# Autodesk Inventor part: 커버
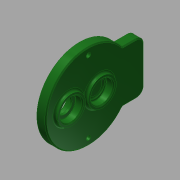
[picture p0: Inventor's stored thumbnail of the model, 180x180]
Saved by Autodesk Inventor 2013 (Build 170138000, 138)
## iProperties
Created: 2016-02
Part Number: 커버
Material: 일반
Document SubType Name: Modeling
Designer: mduedu
Density: 1 g/cm^3
Mass: 58.0249 g
Surface Area: 178.476 cm^2
Volume: 58.0249 cm^3
Author: mduedu
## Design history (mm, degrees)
sketch "스케치1"
  geometry: C1 r 43 at (0, 0); 1 further point
  constraints: 1 centre point, 1 coincident
  dimensions: "d0" = 86 diameter of C1
extrude "돌출1" new body sketch "스케치1" distance "d1" = 9; taper "d2" = 0 deg
sketch "스케치2"
  geometry: C1 r 14 at (0, 11); 1 further point
  constraints: 1 centre point, 1 vertical alignment
  dimensions: "d3" = 28 diameter of C1; "d6" = 11 distance of C1.centre point (0, 0)
extrude "돌출2" join sketch "스케치2" distance "d7" = 3; taper "d8" = 0 deg
sketch "스케치3"
  geometry: C1 r 14 at (0, -20); 1 further point
  constraints: 1 centre point, 1 vertical alignment
  dimensions: "d9" = 28 diameter of C1; "d10" = 20 distance of C1.centre point (0, 0)
extrude "돌출3" join sketch "스케치3" distance "d11" = 3; taper "d12" = 0 deg
hole "구멍1" diameter "d15" = 22; stored, may be unused: countersink angle "d19" = 90 deg, drill point angle "d21" = 0 deg; dims "d13" = 10, "d14" = 10, "d16" = 6, "d17" = 4, "d18" = 2, "d20" = 7
hole "구멍2" diameter "d24" = 18; stored, may be unused: countersink angle "d28" = 90 deg, drill point angle "d30" = 0 deg; dims "d22" = 10, "d23" = 10, "d25" = 6, "d26" = 4, "d27" = 2, "d29" = 1
hole "구멍3" diameter "d33" = 22; stored, may be unused: countersink angle "d37" = 90 deg, drill point angle "d39" = 0 deg; dims "d34" = 6, "d35" = 4, "d36" = 2, "d38" = 7, "d73" = 10, "d74" = 10
sketch "스케치7"
  geometry: L1 (-26, 34.249)-(26, 34.249); L2 (26, 34.249)-(26, 56); L3 (26, 56)-(-26, 56); L4 (-26, 56)-(-26, 34.249); A1 r 43 centre (0, 0) between (-26, 34.249) and (26, 34.249) reference; 1 further point
  constraints: 8 end point, 2 parallel, 2 point on circle, 1 horizontal, 1 perpendicular
  dimensions: "d95" = 52 distance of L2.end L3.end; "d97" = 56 distance from line of L3 point (0, 0)
extrude "돌출5" join sketch "스케치7" stored distance "d98" = 10; taper "d99" = 0 deg
sketch "스케치4"
  geometry: C1 r 14 at (0, -20) reference; C2 r 18 at (0, -20); 1 further point
  constraints: 1 centre point, 1 coincident
  dimensions: "d40" = 36 diameter of C2
extrude "돌출4" join sketch "스케치4" distance "d41" = 4; taper "d42" = 0 deg
hole "구멍4" diameter "d45" = 22; stored, may be unused: countersink angle "d49" = 90 deg, drill point angle "d51" = 0 deg; dims "d43" = 10, "d44" = 10, "d46" = 6, "d47" = 4, "d48" = 2, "d50" = 7
hole "구멍5" diameter "d54" = 15; stored, may be unused: countersink angle "d58" = 90 deg, drill point angle "d60" = 0 deg; dims "d52" = 10, "d53" = 10, "d55" = 6, "d56" = 4, "d57" = 2, "d59" = 7
fillet "모깎기1" dims "d61" = 0.3
fillet "모깎기2" dims "d62" = 2
chamfer "모따기1" distance "d63" = 1; stored, may be unused: second distance "d64" = 2, angle "d65" = 45 deg
fillet "모깎기6" dims "d88" = 2
sketch "스케치5" dims "d67" = 72
  geometry: 4 further points
  constraints: 2 horizontal alignment, 1 coincident, 5 other
  dimensions: "d71" = 360 deg dimension on point (0, 0) point (-36, 0) (derived)
fillet "모깎기4" dims "d75" = 2
sketch "스케치6"
  geometry: 2 further points
hole "구멍6" sketch "스케치6" at (36, 0), (-36, 0) diameter "d76" = 4.5; stored, may be unused: countersink angle "d80" = 90 deg, drill point angle "d82" = 0 deg; dims "d77" = 6, "d78" = 8, "d79" = 4.6, "d81" = 8
fillet "모깎기7" dims "d100" = 8, "d101" = 2
chamfer "모따기2" distance "d90" = 1; stored, may be unused: second distance "d91" = 2, angle "d92" = 45 deg
node "솔리드1"
node "절단 모서리 투영1"
